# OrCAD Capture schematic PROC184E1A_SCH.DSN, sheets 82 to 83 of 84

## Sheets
82 61. AUDIO I/F - CODEC: size C; title: AUDIO I/F CODEC; note: PROC184_SCH
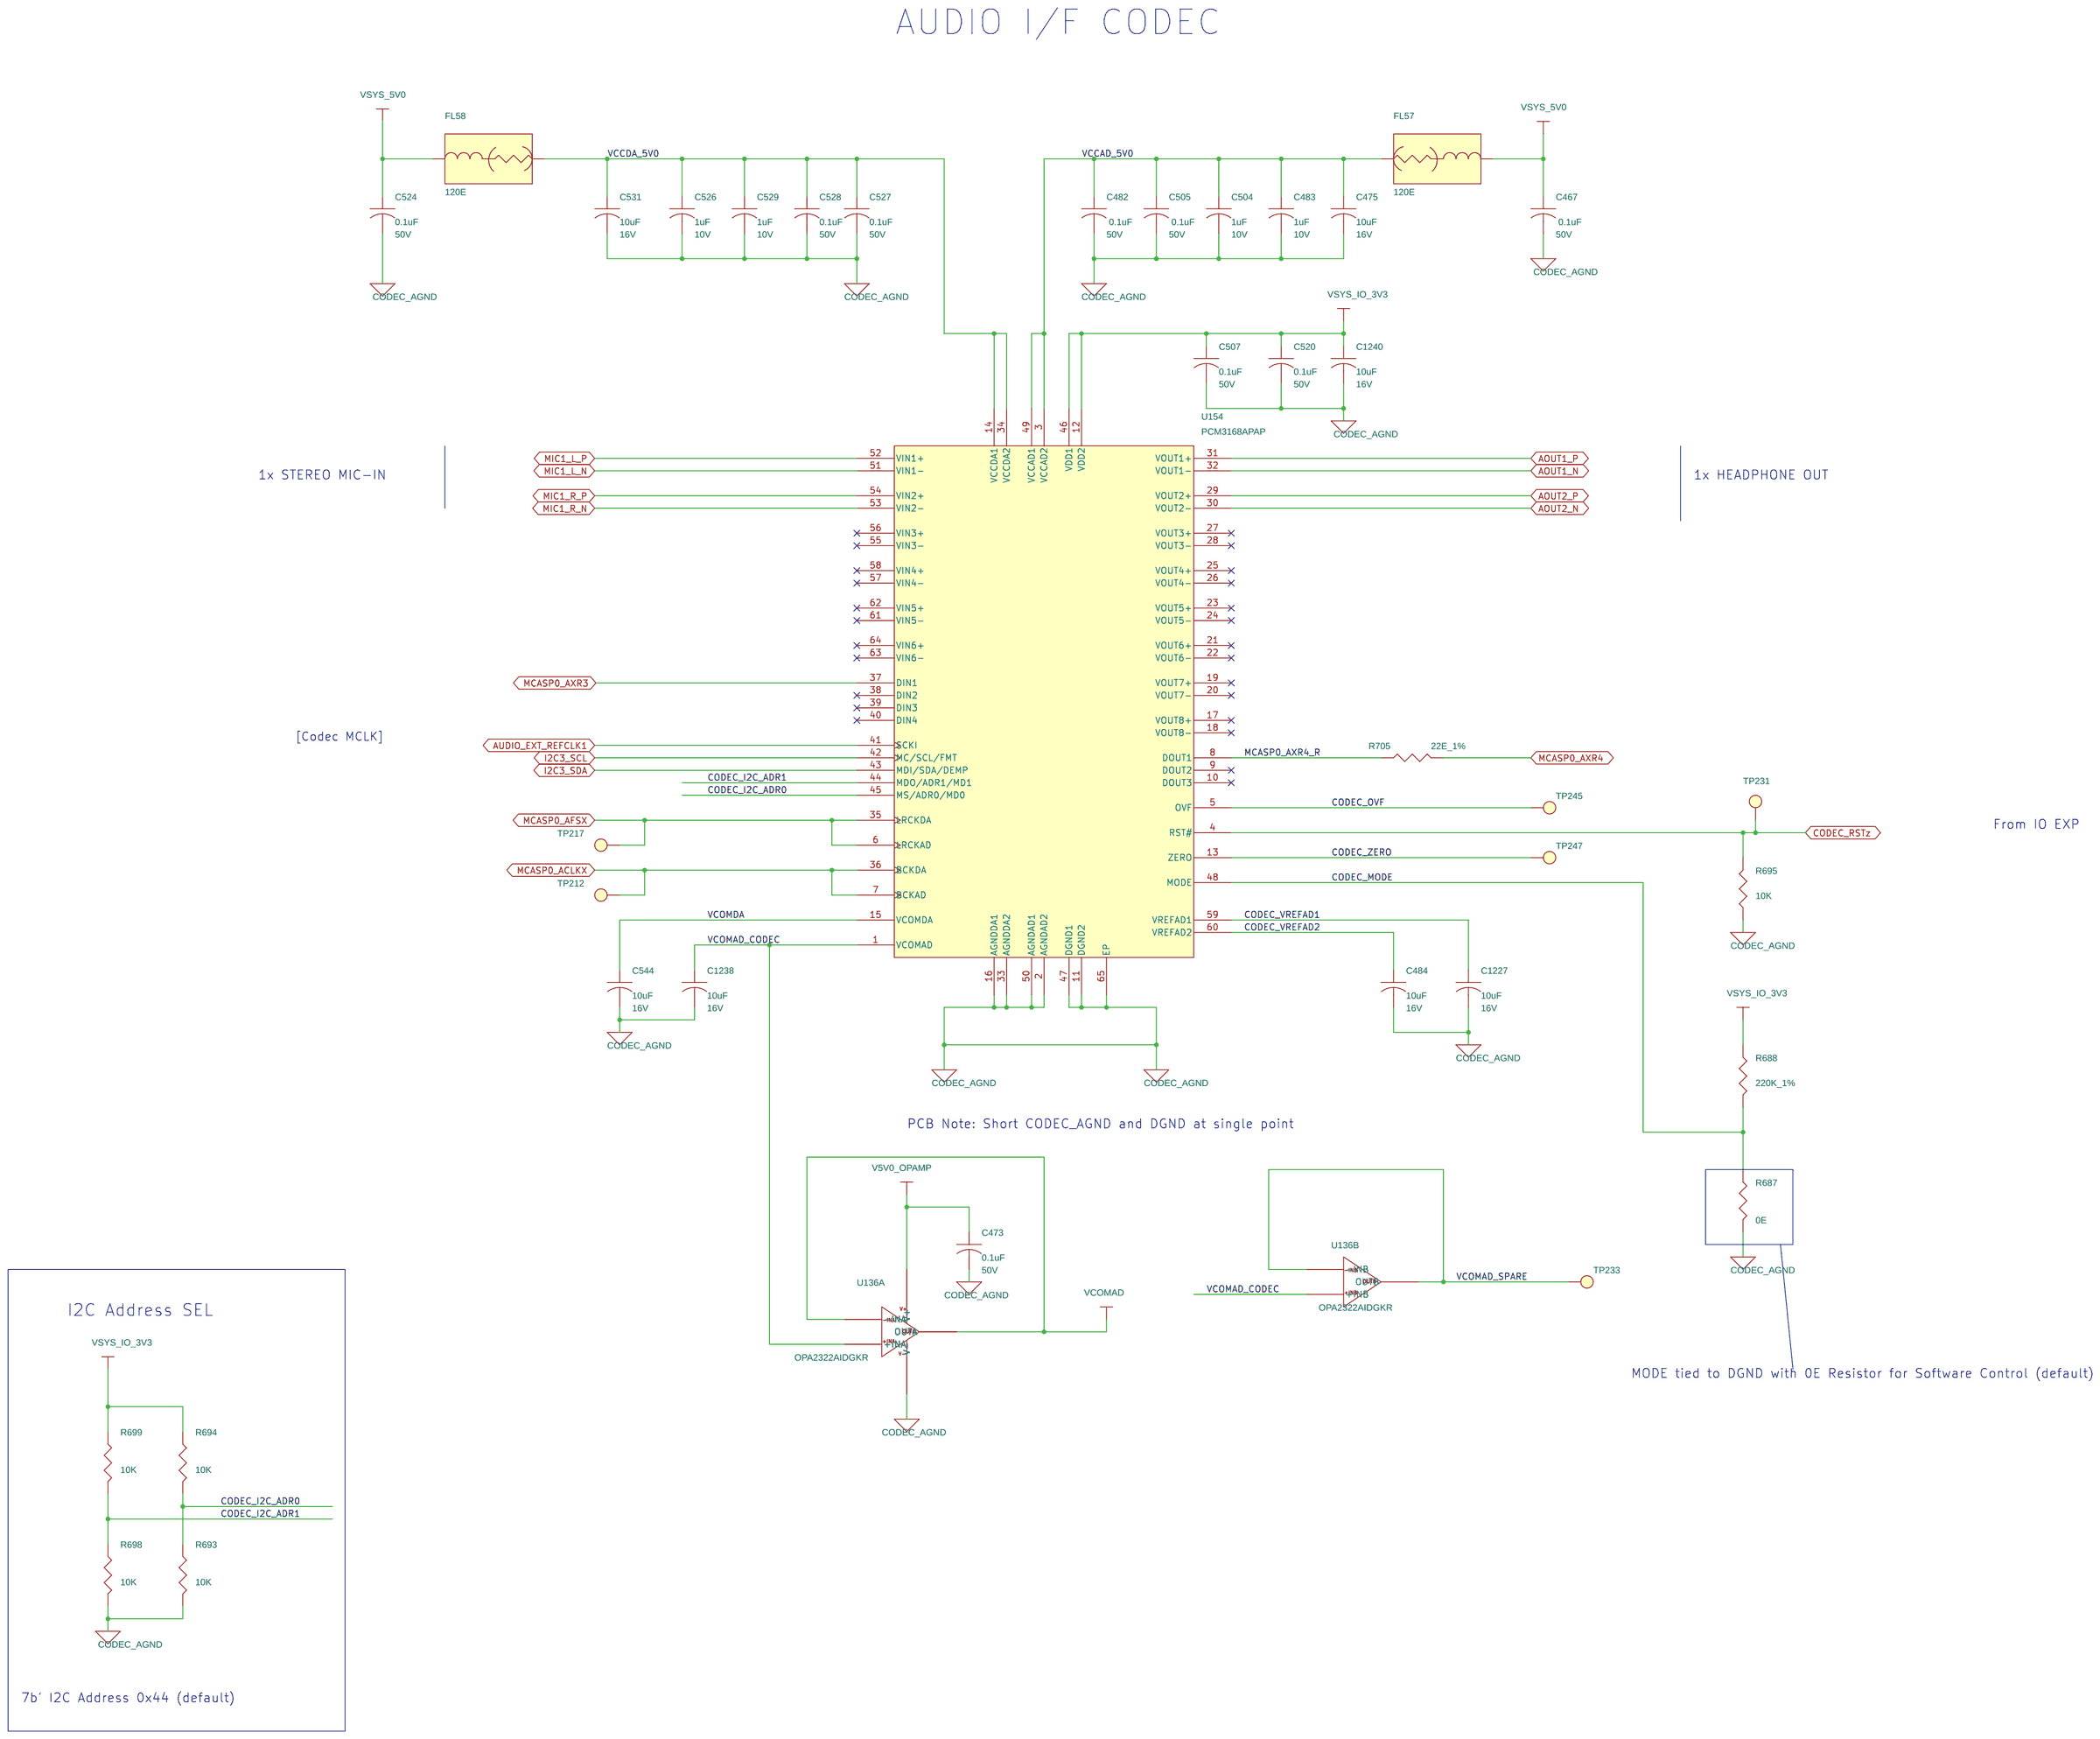
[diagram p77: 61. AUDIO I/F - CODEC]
83 63. AUDIO I/F - STEREO LOUT 1: size C; title: AUDIO I/F - STEREO LINE OUT & HP OUT# 1; note: PROC184_SCH
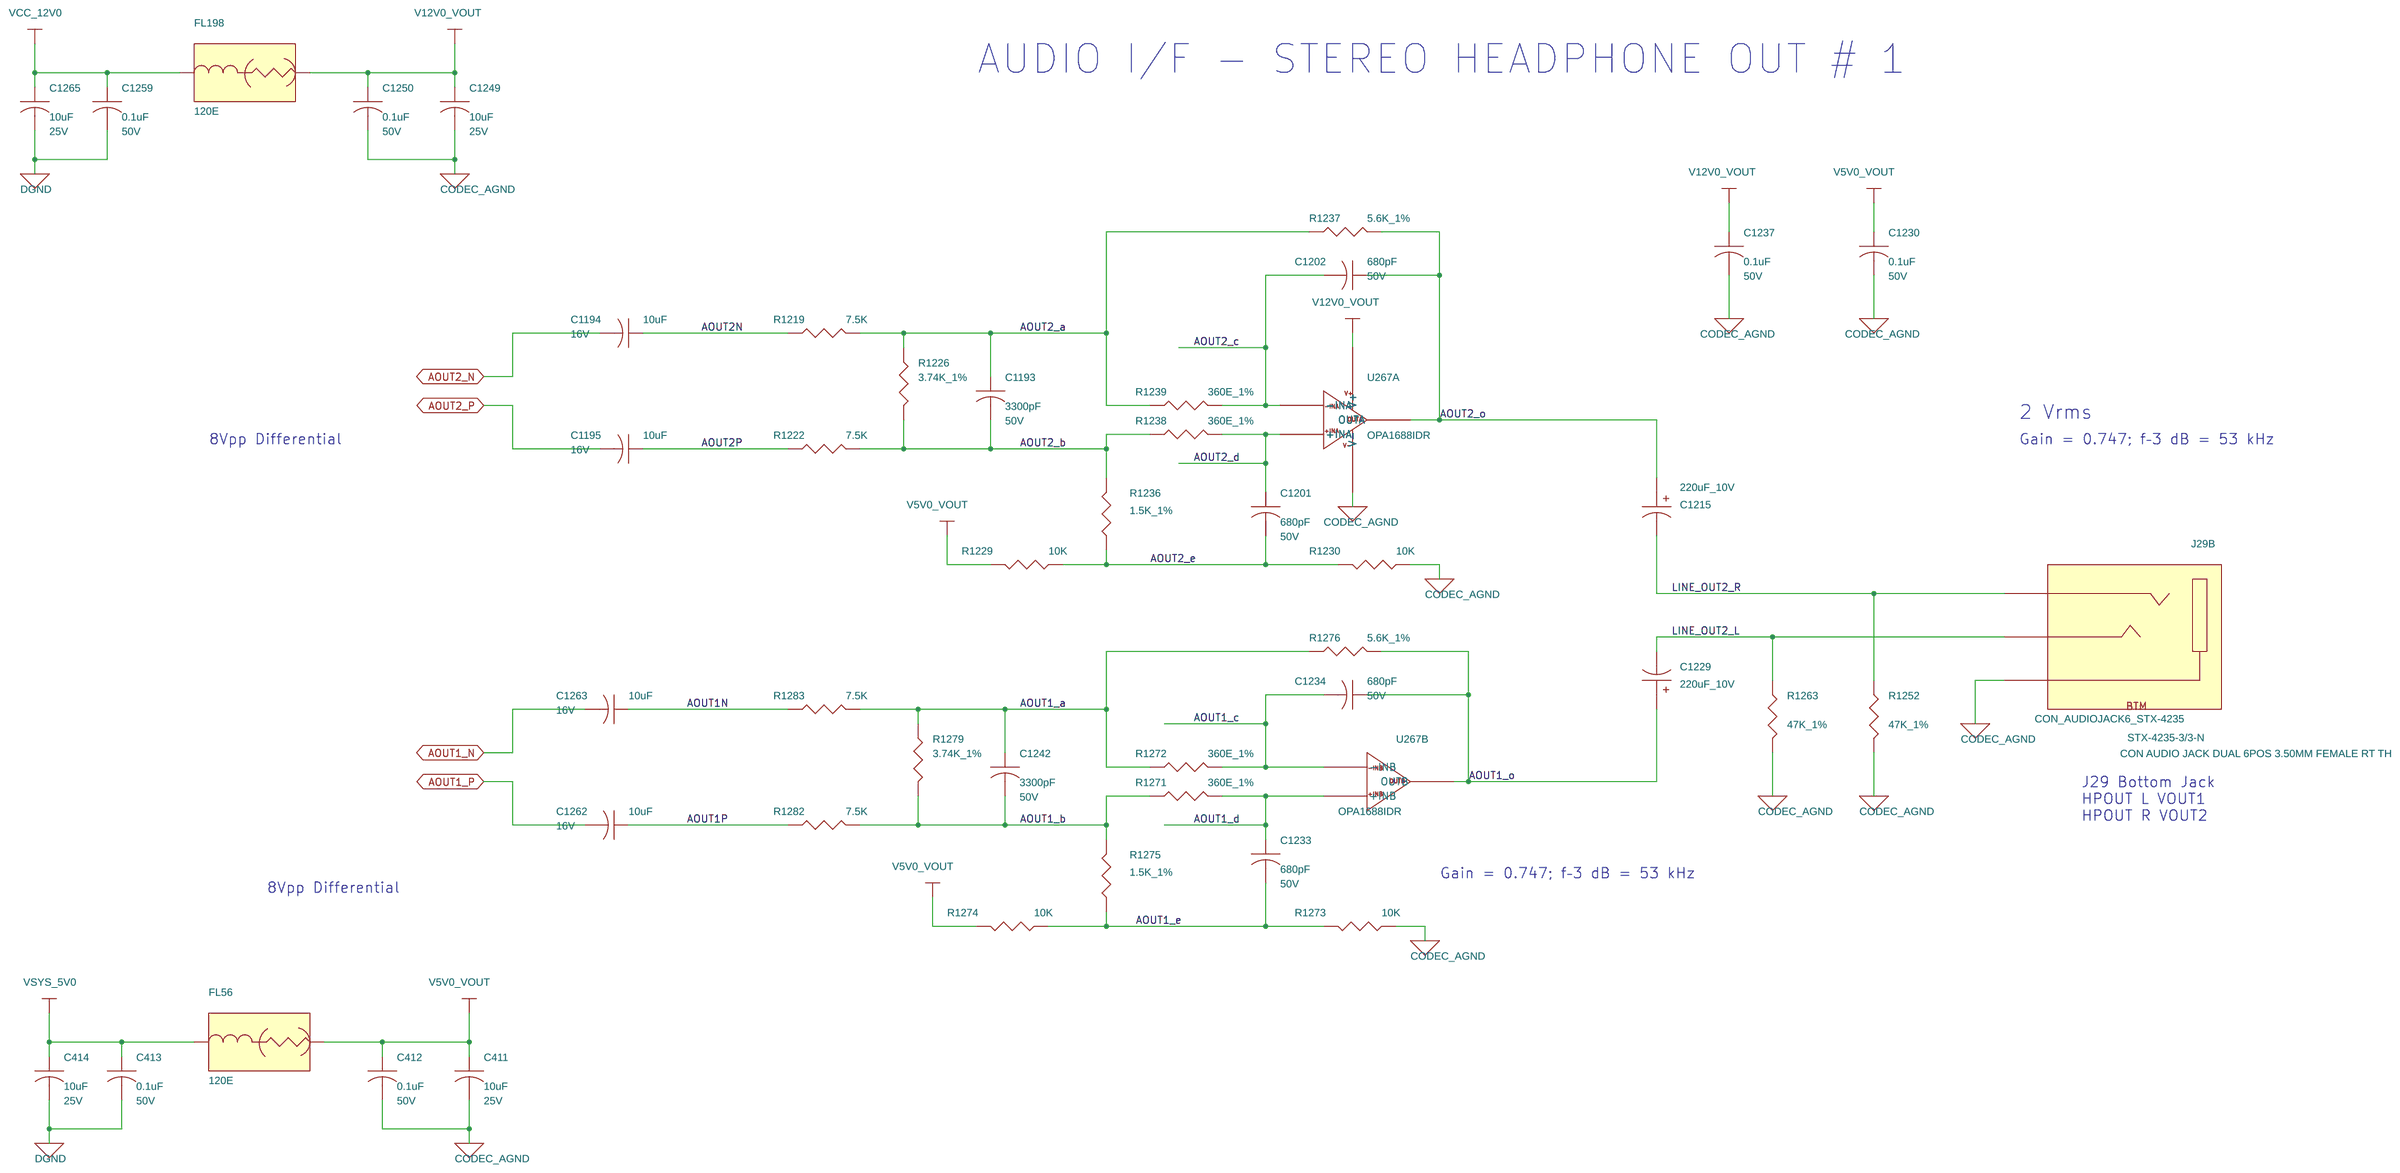
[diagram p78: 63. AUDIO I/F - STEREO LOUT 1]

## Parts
sheet 61. AUDIO I/F - CODEC
C467  0.1uF  [CAP0402_0-75]
C473  0.1uF  [CAP0402_0-75]
C475  10uF  [CAP0805_1-5]
C482  0.1uF  [CAP0402_0-75]
C483  1uF  [CAP0402_0-75]
C484  10uF  [CAP0805_1-5]
C504  1uF  [CAP0402_0-75]
C505  0.1uF  [CAP0402_0-75]
C507  0.1uF  [CAP0402_0-75]
C520  0.1uF  [CAP0402_0-75]
C524  0.1uF  [CAP0402_0-75]
C526  1uF  [CAP0402_0-75]
C527  0.1uF  [CAP0402_0-75]
C528  0.1uF  [CAP0402_0-75]
C529  1uF  [CAP0402_0-75]
C531  10uF  [CAP0805_1-5]
C544  10uF  [CAP0805_1-5]
C1227  10uF  [CAP0805_1-5]
C1238  10uF  [CAP0805_1-5]
C1240  10uF  [CAP0805_1-5]
FL57  120E  [EMIFIL_BLM15A_0402_0-6]
FL58  120E  [EMIFIL_BLM15A_0402_0-6]
R687  0E  [RES0402_0-5]
R688  220K_1%  [RES0402_0-5]
R693  10K  [RES0402_0-5]
R694  10K  [RES0402_0-5]
R695  10K  [RES0402_0-5]
R698  10K  [RES0402_0-5]
R699  10K  [RES0402_0-5]
R705  22E_1%  [RES0402_0-5]
TP212  TP40_SMD  [TP40_SMD]
TP217  TP40_SMD  [TP40_SMD]
TP231  TP40_SMD  [TP40_SMD]
TP233  TP40_SMD  [TP40_SMD]
TP245  TP40_SMD  [TP40_SMD]
TP247  TP40_SMD  [TP40_SMD]
U136  OPA2322AIDGKR  [VSSOP8_25-59_120X120_1-1]  (sections A,B)
U154  PCM3168APAP  [HTQFP64_19-68_400X400_1-2_EP7-3X7]
sheet 62. AUDIO I/F - STEREO MIC #1
J29  CON_AUDIOJACK6_STX-4235  [CON_AV6_STX-4235-3-3_S_R_T_26]  (sections A,B)
sheet 63. AUDIO I/F - STEREO LOUT 1
C411  10uF  [CAP0603_1-25]
C412  0.1uF  [CAP0402_0-75]
C413  0.1uF  [CAP0402_0-75]
C414  10uF  [CAP0603_1-25]
C1193  3300pF  [CAP0402_0-75]
C1194  10uF  [CAP0805_1-5]
C1195  10uF  [CAP0805_1-5]
C1201  680pF  [CAP0402_0-75]
C1202  680pF  [CAP0402_0-75]
C1215  220uF_10V  [CAPT3528T_1-25]
C1229  220uF_10V  [CAPT3528T_1-25]
C1230  0.1uF  [CAP0402_0-75]
C1233  680pF  [CAP0402_0-75]
C1234  680pF  [CAP0402_0-75]
C1237  0.1uF  [CAP0402_0-75]
C1242  3300pF  [CAP0402_0-75]
C1249  10uF  [CAP0603_1-25]
C1250  0.1uF  [CAP0402_0-75]
C1259  0.1uF  [CAP0402_0-75]
C1262  10uF  [CAP0805_1-5]
C1263  10uF  [CAP0805_1-5]
C1265  10uF  [CAP0603_1-25]
FL56  120E  [EMIFIL_BLM15A_0402_0-6]
FL198  120E  [EMIFIL_BLM15A_0402_0-6]
R1219  7.5K  [RES0402_0-5]
R1222  7.5K  [RES0402_0-5]
R1226  3.74K_1%  [RES0402_0-5]
R1229  10K  [RES0402_0-5]
R1230  10K  [RES0402_0-5]
R1236  1.5K_1%  [RES0402_0-5]
R1237  5.6K_1%  [RES0402_0-5]
R1238  360E_1%  [RES0402_0-5]
R1239  360E_1%  [RES0402_0-5]
R1252  47K_1%  [RES0402_0-5]
R1263  47K_1%  [RES0402_0-5]
R1271  360E_1%  [RES0402_0-5]
R1272  360E_1%  [RES0402_0-5]
R1273  10K  [RES0402_0-5]
R1274  10K  [RES0402_0-5]
R1275  1.5K_1%  [RES0402_0-5]
R1276  5.6K_1%  [RES0402_0-5]
R1279  3.74K_1%  [RES0402_0-5]
R1282  7.5K  [RES0402_0-5]
R1283  7.5K  [RES0402_0-5]
U267  OPA1688IDR  [SOIC8_1-8]  (sections A,B)

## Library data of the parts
C412 C413 C467 C473 C482 C505 C507 C520 C524 C527 C528 C1230 C1237 C1250 C1259 = CAP: CAP CERAMIC 0.1uF 50V 10% X7R 0402; Automotive Alternate_mfr_name: TDK; Automotive Alternate_mfr_part_number: CGA2B3X7R1H104K050BB; Chkd/date: MANIRAJA/261020; Crtd /date: ALVY/211020; Custom_Duty: 15%; Customs_HS_Code: 85322990; Direct Alternate_mfr_name: TDK; Direct Alternate_mfr_part_number: C1005X7R1H104K050BE; Distributor_name: DIGIKEY; Distributor_part_number: 490-10700-1-ND; Footprint Path: Y:\MIS_DATABASE\Library\ALTIUM_TOOL\PCB_FOOTPRINTS\Altium_Footprint_Lib.PcbLib; Height: 0.55MM; Library Path: Y:\MIS_DATABASE\Library\ALTIUM_TOOL\SCHEMATICS_PARTS\MS_DISCRETE_Library.schlib; Manufacturer: MURATA; Mfr_name: MURATA; Mfr_part_number: GRM155R71H104KE14D; Mistral Part No: 120011100014-R; Package: 0402; Part_type: CAPACITORS\CERAMIC; Project: J7_CP; RoHS: RoHS; Temperature: -55°C+125°C; Tolerance: 10%; Voltage: 50V; Wattage: NA; Weight: 3.1mg; Datasheet: Y:\MIS_DATABASE\DATASHEETS\CAPACITORS\GRM155R71H104KE14.PDF
C475 C484 C531 C544 C1194 C1195 C1227 C1238 C1240 C1262 C1263 = CAP: CAP CERAMIC 10uF 16V 10% X5R 0805; Automotive Alternate_mfr_name: TDK; Automotive Alternate_mfr_part_number: CGA4J1X7S1C106K125AC; Chkd/date: SHREESHAIL/220506; Crtd /date: MAZHAR/150506; Custom_Duty: 15%; Customs_HS_Code: 85322990; Direct Alternate_mfr_name: TDK; Direct Alternate_mfr_part_number: C2012X7S1C106K125AC; Distributor_name: DIGIKEY; Distributor_part_number: 490-3886-1-ND; Footprint Path: Y:\MIS_DATABASE\Library\ALTIUM_TOOL\PCB_FOOTPRINTS\Altium_Footprint_Lib.PcbLib; Height: 1.35MM; Library Path: Y:\MIS_DATABASE\Library\ALTIUM_TOOL\SCHEMATICS_PARTS\MS_DISCRETE_Library.schlib; Manufacturer: MURATA; Mfr_name: MURATA; Mfr_part_number: GRM21BR61C106KE15L; Mistral Part No: 120009030205-R; Package: 0805; Part_type: CAPACITORS\CERAMIC; Project: VOCERA; RoHS: RoHS; Temperature: -55°C+85°C; Tolerance: 10%; Voltage: 16V; Wattage: NA; Weight: 9.5mg; Datasheet: Y:\MIS_DATABASE\DATASHEETS\CAPACITORS\MURATA-GXX-SER_NOV17.PDF
C483 C504 C526 C529 = CAP: CAP CERAMIC 1uF 10V 10% X7S AUTO 0402; Automotive Alternate_mfr_name: TAIYO YUDEN; Automotive Alternate_mfr_part_number: EMK105BJ105KVHF; Chkd/date: MANIRAJA/100918; Crtd /date: ALVY/100918; Custom_Duty: 15%; Customs_HS_Code: 85322990; Direct Alternate_mfr_name: YAGEO AMERICA; Direct Alternate_mfr_part_number: CC0402KRX5R7BB105; Distributor_name: DIGIKEY; Distributor_part_number: 490-13409-1-ND; Footprint Path: Y:\MIS_DATABASE\Library\ALTIUM_TOOL\PCB_FOOTPRINTS\Altium_Footprint_Lib.PcbLib; Height: 0.70MM; Library Path: Y:\MIS_DATABASE\Library\ALTIUM_TOOL\SCHEMATICS_PARTS\MS_DISCRETE_Library.schlib; Manufacturer: TDK CORPORATION; Mfr_name: MURATA; Mfr_part_number: GCM155C71A105KE38D; Mistral Part No: 120018090021-R; Package: 0402; Part_type: CAPACITORS\CERAMIC; Project: SMART-M_SCRIPTALK_PB; RoHS: RoHS; Temperature: -55°C+125°C; Tolerance: 10%; Voltage: 10V; Wattage: NA; Weight: 6mg; Datasheet: Y:\MIS_DATABASE\DATASHEETS\CAPACITORS\MURATA-GCM-SER.PDF
FL56-FL58 FL198 = EMIFILTER_IND: IND FERRITE BEAD CHIP 120E 1.3A 0402; Automotive Alternate_mfr_name: TDK; Automotive Alternate_mfr_part_number: MPZ1005S121CTD25; Chkd/date: VASANTHA/010117; Crtd /date: CHAITHANYA/150312; Custom_Duty: 24%; Customs_HS_Code: 85437099; Direct Alternate_mfr_name: TDK; Direct Alternate_mfr_part_number: MPZ1005S121CT000; Distributor_name: DIGIKEY; Distributor_part_number: 490-5203-1-ND; Footprint Path: Y:\MIS_DATABASE\Library\ALTIUM_TOOL\PCB_FOOTPRINTS\Altium_Footprint_Lib.PcbLib; Height: 0.55MM; Library Path: Y:\MIS_DATABASE\Library\ALTIUM_TOOL\SCHEMATICS_PARTS\MS_FILTER_Library.schlib; Manufacturer: MURATA; Mfr_name: MURATA; Mfr_part_number: BLM15PD121SN1D; Mistral Part No: 130012030043-R; Package: 0402; Part_type: FILTER; Project: GEN_3-8; RoHS: RoHS; Temperature: -55°C+125°C; Tolerance: 25%; Voltage: NA; Wattage: NA; Weight: 0.65mg; Datasheet: Y:\MIS_DATABASE\DATASHEETS\DISCRETES\INDUCTORS\BLM15X-SER.PDF
R687 = RESISTOR: RES 0E 1/10W JUMPER 0402; Chkd/date: VASANTHA/061216; Crtd /date: NAVEED/201014; Custom_Duty: 15%; Customs_HS_Code: 85332119; Distributor_name: DIGIKEY; Distributor_part_number: P0.0JCT-ND; Footprint Path: Y:\MIS_DATABASE\Library\ALTIUM_TOOL\PCB_FOOTPRINTS\Altium_Footprint_Lib.PcbLib; Height: 0.40MM; IBISSP_MODLES: VALUE REPEATING 2 TIME; Library Path: Y:\MIS_DATABASE\Library\ALTIUM_TOOL\SCHEMATICS_PARTS\MS_DISCRETE_Library.schlib; Manufacturer: PANASONIC-ECG; Mfr_name: PANASONIC-ECG; Mfr_part_number: ERJ-2GE0R00X; Mistral Part No: 110018030052-R; Package: 0402; Part_type: RESISTORS\FIXED; Project: AEGIS POM; RoHS: RoHS; Temperature: -55°C+155°C; Tolerance: NA; Voltage: NA; Wattage: 1/10W; Weight: 0.8mg; Datasheet: Y:\MIS_DATABASE\DATASHEETS\RESISTORS\PAN-ERJSER_NOV17.PDF
R688 = RESISTOR: RES 220K 1/16W 1% 0402; Assembly_Instruction: DNI; Chkd/date: MANIRAJA/230817; Crtd /date: MANIRAJA/230817; Custom_Duty: 15%; Customs_HS_Code: 85332119; Distributor_name: DIGIKEY; Distributor_part_number: 541-220KLCT-ND; Footprint Path: Y:\MIS_DATABASE\Library\ALTIUM_TOOL\PCB_FOOTPRINTS\Altium_Footprint_Lib.PcbLib; Height: 0.40MM; Library Path: Y:\MIS_DATABASE\Library\ALTIUM_TOOL\SCHEMATICS_PARTS\MS_DISCRETE_Library.schlib; Manufacturer: VISHAY; Mfr_name: VISHAY; Mfr_part_number: CRCW0402220KFKED; Mistral Part No: 110017080025-R; Package: 0402; Part_type: RESISTORS\FIXED; Project: TI_MAXIE_CPB; RoHS: RoHS; Temperature: -55°C+155°C; Tolerance: 1%; Voltage: NA; Wattage: 1/16W; Weight: 0.65mg; Datasheet: Y:\MIS_DATABASE\DATASHEETS\RESISTORS\CRCW0603.PDF
R693 R695 R698 R1229 R1230 R1273 R1274 = RESISTOR: RES 10K 1/16W 5% 0402; Chkd/date: VASANTHA/061216; Crtd /date: MAZHAR/230805; Custom_Duty: 15%; Customs_HS_Code: 85332119; Distributor_name: DIGIKEY; Distributor_part_number: 311-10KJRCT-ND; Footprint Path: Y:\MIS_DATABASE\Library\ALTIUM_TOOL\PCB_FOOTPRINTS\Altium_Footprint_Lib.PcbLib; Height: 0.40MM; Library Path: Y:\MIS_DATABASE\Library\ALTIUM_TOOL\SCHEMATICS_PARTS\MS_DISCRETE_Library.schlib; Manufacturer: YAGEO AMERICA; Mfr_name: YAGEO AMERICA; Mfr_part_number: RC0402JR-0710KL; Mistral Part No: 110011060021-R; Package: 0402; Part_type: RESISTORS\FIXED; Project: HSE; RoHS: RoHS; Temperature: -55°C+155°C; Tolerance: 5%; Voltage: NA; Wattage: 1/16W; Weight: 0.65mg; Datasheet: Y:\MIS_DATABASE\DATASHEETS\RESISTORS\RCXXXXL-SER_MAR18.PDF
R694 R699 = RESISTOR: RES 10K 1/16W 5% 0402; Assembly_Instruction: DNI; Chkd/date: VASANTHA/061216; Crtd /date: MAZHAR/230805; Custom_Duty: 15%; Customs_HS_Code: 85332119; Distributor_name: DIGIKEY; Distributor_part_number: 311-10KJRCT-ND; Footprint Path: Y:\MIS_DATABASE\Library\ALTIUM_TOOL\PCB_FOOTPRINTS\Altium_Footprint_Lib.PcbLib; Height: 0.40MM; Library Path: Y:\MIS_DATABASE\Library\ALTIUM_TOOL\SCHEMATICS_PARTS\MS_DISCRETE_Library.schlib; Manufacturer: YAGEO AMERICA; Mfr_name: YAGEO AMERICA; Mfr_part_number: RC0402JR-0710KL; Mistral Part No: 110011060021-R; Package: 0402; Part_type: RESISTORS\FIXED; Project: HSE; RoHS: RoHS; Temperature: -55°C+155°C; Tolerance: 5%; Voltage: NA; Wattage: 1/16W; Weight: 0.65mg; Datasheet: Y:\MIS_DATABASE\DATASHEETS\RESISTORS\RCXXXXL-SER_MAR18.PDF
R705 = RESISTOR: RES 22E 1/16W 1% 0402; Chkd/date: SUHAS/290910; Crtd /date: MAZHAR/090909; Cust_part_number: 4700-80047E; Custom_Duty: 15%; Customs_HS_Code: 85332119; Distributor_name: DIGIKEY; Distributor_part_number: 311-22.0LRCT-ND; Footprint Path: Y:\MIS_DATABASE\Library\ALTIUM_TOOL\PCB_FOOTPRINTS\Altium_Footprint_Lib.PcbLib; Height: 0.40MM; Library Path: Y:\MIS_DATABASE\Library\ALTIUM_TOOL\SCHEMATICS_PARTS\MS_DISCRETE_Library.schlib; Manufacturer: YAGEO AMERICA; Mfr_name: YAGEO AMERICA; Mfr_part_number: RC0402FR-0722RL; Mistral Part No: 110009090004-R; Package: 0402; Part_type: RESISTORS\FIXED; Project: VMEFMCD; RoHS: RoHS; Temperature: -55°C+155°C; Tolerance: 1%; Voltage: NA; Wattage: 1/16W; Weight: 0.65mg; Datasheet: Y:\MIS_DATABASE\DATASHEETS\RESISTORS\RCXXXXL-SER_MAR18.PDF
TP212 TP217 TP231 TP233 TP245 TP247 = TESTPOINT: TESTPOINT CIR 40 SMD; Chkd/date: MAZHAR/190505; Crtd /date: MAZHAR/190505; Distributor_name: NA; Distributor_part_number: NA; Footprint Path: Y:\MIS_DATABASE\Library\ALTIUM_TOOL\PCB_FOOTPRINTS\Altium_Footprint_Lib.PcbLib; Height: NA; Library Path: Y:\MIS_DATABASE\Library\ALTIUM_TOOL\SCHEMATICS_PARTS\MS_DISCRETE_Library.schlib; MECHANICAL 3D STEP FILE: NA; Manufacturer: LOCAL; Mfr_name: LOCAL; Mistral Part No: 130009030933; Package: SMD; Project: RAINIER-3; RoHS: NA; Temperature: NA; Tolerance: NA; Voltage: NA; Wattage: NA; Weight: NA; Datasheet: NA
U136 = OPA2350UA_SOIC8: IC 20MHz 1.8V LOW NOISE RRI/O CMOS OPAMP VSSOP8; Automotive Alternate_mfr_name: TEXAS INSTRUMENTS; Automotive Alternate_mfr_part_number: OPA2322AQDGKRQ1; Chkd/date: MANIRAJA/161018; Crtd /date: ALVY/161018; Custom_Duty: 15%; Customs_HS_Code: 85423100; Distributor_name: DIGIKEY; Distributor_part_number: 296-41349-1-ND; Footprint Path: Y:\MIS_DATABASE\Library\ALTIUM_TOOL\PCB_FOOTPRINTS\Altium_Footprint_Lib.PcbLib; Height: 1.10MM; Library Path: Y:\MIS_DATABASE\Library\ALTIUM_TOOL\SCHEMATICS_PARTS\MS_OPAMP_Library.schlib; Manufacturer: TEXAS INSTRUMENTS; Mfr_name: TEXAS INSTRUMENTS; Mistral Part No: 140118100019-R; Package: VSSOP8; Part_type: ICS\ANALOG\OPAMP; Project: TI_J7ES_EVM_CP; RoHS: RoHS; Temperature: -40°C+125°C; Tolerance: NA; Voltage: NA; Wattage: NA; Weight: 26.5mg; Datasheet: Y:\MIS_DATABASE\DATASHEETS\ICS\OPAMP\OPA2322XX.PDF
U154 = PCM3168APAP_HTQFP64_TI: IC 24BIT 96KHz/192KHz 6-IN/8-OUT AUDIO CODEC WITH DIFFERENTIAL IN/OUT HTQFP64; Automotive Alternate_mfr_name: TEXAS INSTRUMENTS; Automotive Alternate_mfr_part_number: PCM3168ATPAPRQ1; Chkd/date: MANIRAJA/140618; Crtd /date: ALVY/140618; Custom_Duty: 15%; Customs_HS_Code: 85423100; Distributor_name: DIGIKEY; Distributor_part_number: 296-23899-5-ND; Footprint Path: Y:\MIS_DATABASE\Library\ALTIUM_TOOL\PCB_FOOTPRINTS\Altium_Footprint_Lib.PcbLib; Height: 1.20MM; Library Path: Y:\MIS_DATABASE\Library\ALTIUM_TOOL\SCHEMATICS_PARTS\MS_TELECOM_Library.schlib; Library Ref: PCM3168APAP_HTQFP64; Manufacturer: TEXAS INSTRUMENTS; Mfr_name: TEXAS INSTRUMENTS; Mistral Part No: 143018060003-R; Package: HTQFP64; Part_type: ICS\TELECOM\CODEC; Project: TI_J7SVB_FMZ-BOARD; RoHS: RoHS; Temperature: -40°C+85°C; Tolerance: NA; Voltage: NA; Wattage: NA; Weight: 258.2mg; Datasheet: Y:\MIS_DATABASE\DATASHEETS\ICS\DIGITAL\CODEC\PCM3168A.PDF
J29 = CON_AUDIOJACK6_STX-4235-3_3: CON AUDIO JACK DUAL 6POS 3.50MM FEMALE RT TH; Chkd/date: MANIRAJA/090818; Crtd /date: ALVY/080818; Custom_Duty: 24%; Customs_HS_Code: 85369090; Distributor_name: MOUSER; Distributor_part_number: 806-STX-4235-3/3-N; Footprint Path: Y:\MIS_DATABASE\Library\ALTIUM_TOOL\PCB_FOOTPRINTS\Altium_Footprint_Lib.PcbLib; Height: 26.00MM; Library Path: Y:\MIS_DATABASE\Library\ALTIUM_TOOL\SCHEMATICS_PARTS\MS_CONNECTOR_Library.schlib; Library Ref: CON_AUDIOJACK6_STX-4235-3/3; Manufacturer: KYCON; Mfr_name: KYCON; Mfr_part_number: STX-4235-3/3-N; Mistral Part No: 150018080005-R; Package: THRU-HOLE; Part_type: CONNECTOR\JACK; Project: TI_J7ES_EVM_FUSION2_SER_CAP; RoHS: RoHS; Temperature: -25°C+85°C; Tolerance: NA; Voltage: NA; Wattage: NA; Weight: NA; Datasheet: Y:\MIS_DATABASE\DATASHEETS\CONNECTORS\STX-4235-3-3-N.PDF
C411 C414 C1249 C1265 = CAP: CAP CERAMIC 10uF 25V 20% X5R 0603; Automotive Alternate_mfr_name: MURATA; Automotive Alternate_mfr_part_number: GRT188R61E106ME13D; Chkd/date: MANIRAJA/040718; Crtd /date: MANIRAJA/040718; Custom_Duty: 15%; Customs_HS_Code: 85322990; Direct Alternate_mfr_name: TDK; Direct Alternate_mfr_part_number: C1608X5R1E106M080AC; Distributor_name: DIGIKEY; Distributor_part_number: 490-10991-1-ND; Footprint Path: Y:\MIS_DATABASE\Library\ALTIUM_TOOL\PCB_FOOTPRINTS\Altium_Footprint_Lib.PcbLib; Height: 1.20MM; Library Path: Y:\MIS_DATABASE\Library\ALTIUM_TOOL\SCHEMATICS_PARTS\MS_DISCRETE_Library.schlib; Manufacturer: MURATA; Mfr_name: MURATA; Mfr_part_number: ZRB18AR61E106ME01L; Mistral Part No: 120018070001-R; Package: 0603; Part_type: CAPACITORS\CERAMIC; Project: CABS_VME_DIO; RoHS: RoHS; Temperature: -55°C+85°C; Tolerance: 20%; Voltage: 25V; Wattage: NA; Weight: 2mg; Datasheet: Y:\MIS_DATABASE\DATASHEETS\CAPACITORS\ZRB18AR61E106ME01L.PDF
C1193 C1242 = CAP: CAP CERAMIC 3300pF 50V 10% X7R 0402; Automotive Alternate_mfr_name: TDK; Automotive Alternate_mfr_part_number: CGA2B2X7R1H332M050BA; Chkd/date: MANIRAJA/180817; Crtd /date: MANIRAJA/180817; Custom_Duty: 15%; Customs_HS_Code: 85322990; Direct Alternate_mfr_name: SAMSUNG; Direct Alternate_mfr_part_number: CL05B332KB5NNNC; Distributor_name: DIGIKEY; Distributor_part_number: 490-3248-1-ND; Footprint Path: Y:\MIS_DATABASE\Library\ALTIUM_TOOL\PCB_FOOTPRINTS\Altium_Footprint_Lib.PcbLib; Height: 0.55MM; Library Path: Y:\MIS_DATABASE\Library\ALTIUM_TOOL\SCHEMATICS_PARTS\MS_DISCRETE_Library.schlib; Manufacturer: MURATA; Mfr_name: MURATA; Mfr_part_number: GRM155R71H332KA01D; Mistral Part No: 120009030367-R; Package: 0402; Part_type: CAPACITORS\CERAMIC; Project: DM8147_PCI CARD; RoHS: RoHS; Temperature: -55°C+125°C; Tolerance: 10%; Voltage: 50V; Wattage: NA; Weight: 6mg; Datasheet: Y:\MIS_DATABASE\DATASHEETS\CAPACITORS\MURATA-GXX-SER_NOV17.PDF
C1201 C1202 C1233 C1234 = CAP: CAP CERAMIC 680pF 50V 5% X7R 0402; Automotive Alternate_mfr_name: TDK; Automotive Alternate_mfr_part_number: CGA2B2X7R1H681K050BA; Chkd/date: BAVISH/260911; Crtd /date: CHAITHANYA/260911; Custom_Duty: 15%; Customs_HS_Code: 85322990; Direct Alternate_mfr_name: SAMSUNG; Direct Alternate_mfr_part_number: CL05B681KB5NNNC; Distributor_name: DIGIKEY; Distributor_part_number: 478-5270-1-ND; Footprint Path: Y:\MIS_DATABASE\Library\ALTIUM_TOOL\PCB_FOOTPRINTS\Altium_Footprint_Lib.PcbLib; Height: 0.56MM; Library Path: Y:\MIS_DATABASE\Library\ALTIUM_TOOL\SCHEMATICS_PARTS\MS_DISCRETE_Library.schlib; Manufacturer: AVX CORPORATION; Mfr_name: AVX CORPORATION; Mfr_part_number: 04025C681JAT2A; Mistral Part No: 120011090031-R; Package: 0402; Part_type: CAPACITORS\CERAMIC; Project: GEMYC; RoHS: RoHS; Temperature: -55°C+125°C; Tolerance: 5%; Voltage: 50V; Wattage: NA; Weight: 0.65mg; Datasheet: Y:\MIS_DATABASE\DATASHEETS\CAPACITORS\AVX_MLC.PDF
C1215 C1229 = CAP_POL: CAP TANTALUM 220uF 10V 20% ESR 1.3E T3528; Chkd/date: MANIRAJA/081218; Crtd /date: MANIRAJA/081218; Custom_Duty: 15%; Customs_HS_Code: 85322990; Distributor_name: DIGIKEY; Distributor_part_number: 478-6612-1-ND; Footprint Path: Y:\MIS_DATABASE\Library\ALTIUM_TOOL\PCB_FOOTPRINTS\Altium_Footprint_Lib.PcbLib; Height: 1.20MM; Library Path: Y:\MIS_DATABASE\Library\ALTIUM_TOOL\SCHEMATICS_PARTS\MS_DISCRETE_Library.schlib; Manufacturer: AVX CORPORATION; Mfr_name: AVX CORPORATION; Mfr_part_number: TLNT227M010R1300; Mistral Part No: 120018120009-R; Package: T3528; Part_type: CAPACITORS\TANTALUM; Project: TI_J7ES_EVM_CP; RoHS: RoHS; Temperature: -55°C+125°C; Tolerance: 20%; Voltage: 10V; Wattage: NA; Weight: 16mg; Datasheet: Y:\MIS_DATABASE\DATASHEETS\CAPACITORS\AVX_TLN-SER.PDF
R1219 R1222 R1282 R1283 = RESISTOR: RES 7.5K 1/16W 5% 0402; Chkd/date: MAZHAR/280108; Crtd /date: USMAN/280108; Custom_Duty: 15%; Customs_HS_Code: 85332119; Distributor_name: DIGIKEY; Distributor_part_number: 541-7.5KJCT-ND; Footprint Path: Y:\MIS_DATABASE\Library\ALTIUM_TOOL\PCB_FOOTPRINTS\Altium_Footprint_Lib.PcbLib; Height: 0.40MM; Library Path: Y:\MIS_DATABASE\Library\ALTIUM_TOOL\SCHEMATICS_PARTS\MS_DISCRETE_Library.schlib; Manufacturer: VISHAY; Mfr_name: VISHAY; Mfr_part_number: CRCW04027K50JNED; Mistral Part No: 110009031092-R; Package: 0402; Part_type: RESISTORS\FIXED; Project: TELEMETRY ENCODER; RoHS: RoHS; Temperature: -55°C+155°C; Tolerance: 5%; Voltage: NA; Wattage: 1/16W; Weight: 0.65mg; Datasheet: Y:\MIS_DATABASE\DATASHEETS\RESISTORS\CRCW0603.PDF
R1226 R1279 = RESISTOR: RES 3.74K 1/10W 1% 0402; Chkd/date: MAZHAR/151208; Crtd /date: USMAN/031208; Custom_Duty: 15%; Customs_HS_Code: 85332119; Distributor_name: DIGIKEY; Distributor_part_number: P3.74KLCT-ND; Footprint Path: Y:\MIS_DATABASE\Library\ALTIUM_TOOL\PCB_FOOTPRINTS\Altium_Footprint_Lib.PcbLib; Height: 0.40MM; Library Path: Y:\MIS_DATABASE\Library\ALTIUM_TOOL\SCHEMATICS_PARTS\MS_DISCRETE_Library.schlib; Manufacturer: PANASONIC-ECG; Mfr_name: PANASONIC-ECG; Mfr_part_number: ERJ-2RKF3741X; Mistral Part No: 110009030640-R; Package: 0402; Part_type: RESISTORS\FIXED; Project: KHAN_HSST; RoHS: RoHS; Temperature: -55°C+155°C; Tolerance: 1%; Voltage: NA; Wattage: 1/10W; Weight: 0.8mg; Datasheet: Y:\MIS_DATABASE\DATASHEETS\RESISTORS\PAN-ERJSER_NOV17.PDF
R1236 R1275 = RESISTOR: RES 1.5K 1/16W 1% 0402; Chkd/date: VASANTHA/201216; Crtd /date: JEBRAN/250815; Custom_Duty: 15%; Customs_HS_Code: 85332119; Distributor_name: DIGIKEY; Distributor_part_number: 311-1.50KLRCT-ND; Footprint Path: Y:\MIS_DATABASE\Library\ALTIUM_TOOL\PCB_FOOTPRINTS\Altium_Footprint_Lib.PcbLib; Height: 0.40MM; Library Path: Y:\MIS_DATABASE\Library\ALTIUM_TOOL\SCHEMATICS_PARTS\MS_DISCRETE_Library.schlib; Manufacturer: YAGEO AMERICA; Mfr_name: YAGEO AMERICA; Mfr_part_number: RC0402FR-071K5L; Mistral Part No: 110015080041-R; Package: 0402; Part_type: RESISTORS\FIXED; Project: OCTBTS3600; RoHS: RoHS; Temperature: -55°C+155°C; Tolerance: 1%; Voltage: NA; Wattage: 1/16W; Weight: 0.65mg; Datasheet: Y:\MIS_DATABASE\DATASHEETS\RESISTORS\RCXXXXL-SER_MAR18.PDF
R1237 R1276 = RESISTOR: RES 5.6K 1/16W 1% 0402; Chkd/date: MANIRAJA/050517; Crtd /date: MANIRAJA/050517; Custom_Duty: 15%; Customs_HS_Code: 85332119; Distributor_name: DIGIKEY; Distributor_part_number: 311-5.6KLRCT-ND; Footprint Path: Y:\MIS_DATABASE\Library\ALTIUM_TOOL\PCB_FOOTPRINTS\Altium_Footprint_Lib.PcbLib; Height: 0.40MM; Library Path: Y:\MIS_DATABASE\Library\ALTIUM_TOOL\SCHEMATICS_PARTS\MS_DISCRETE_Library.schlib; Manufacturer: YAGEO AMERICA; Mfr_name: YAGEO AMERICA; Mfr_part_number: RC0402FR-075K6L; Mistral Part No: 110011100024-R; Package: 0402; Part_type: RESISTORS\FIXED; Project: GOLDEN-I LITE; RoHS: RoHS; Temperature: -55°C+155°C; Tolerance: 1%; Voltage: NA; Wattage: 1/16W; Weight: 0.65mg; Datasheet: Y:\MIS_DATABASE\DATASHEETS\RESISTORS\RCXXXXL-SER_MAR18.PDF
R1238 R1239 R1271 R1272 = RESISTOR: RES 360E 1/10W 1% 0402; Chkd/date: MANIRAJA/190218; Crtd /date: ALVY/190218; Custom_Duty: 15%; Customs_HS_Code: 85332119; Distributor_name: DIGIKEY; Distributor_part_number: P360LCT-ND; Footprint Path: Y:\MIS_DATABASE\Library\ALTIUM_TOOL\PCB_FOOTPRINTS\Altium_Footprint_Lib.PcbLib; Height: 0.40MM; Library Path: Y:\MIS_DATABASE\Library\ALTIUM_TOOL\SCHEMATICS_PARTS\MS_DISCRETE_Library.schlib; Manufacturer: PANASONIC-ECG; Mfr_name: PANASONIC-ECG; Mfr_part_number: ERJ-2RKF3600X; Mistral Part No: 110018020033-R; Package: 0402; Part_type: RESISTORS\FIXED; Project: GRACO SMART MODULE; RoHS: RoHS; Temperature: -55°C+155°C; Tolerance: 1%; Voltage: NA; Wattage: 1/10W; Weight: 0.8mg; Datasheet: Y:\MIS_DATABASE\DATASHEETS\RESISTORS\PAN-ERJSER_NOV17.PDF
R1252 R1263 = RESISTOR: RES 47K 1/16W 1% 0402; Chkd/date: VASANTHA/060117; Crtd /date: MAZHAR/141206; Custom_Duty: 15%; Customs_HS_Code: 85332119; Distributor_name: DIGIKEY; Distributor_part_number: 311-47.0KLRCT-ND; Footprint Path: Y:\MIS_DATABASE\Library\ALTIUM_TOOL\PCB_FOOTPRINTS\Altium_Footprint_Lib.PcbLib; Height: 0.40MM; Library Path: Y:\MIS_DATABASE\Library\ALTIUM_TOOL\SCHEMATICS_PARTS\MS_DISCRETE_Library.schlib; Manufacturer: YAGEO AMERICA; Mfr_name: YAGEO AMERICA; Mfr_part_number: RC0402FR-0747KL; Mistral Part No: 110009030884-R; Package: 0402; Part_type: RESISTORS\FIXED; Project: ADR1B; RoHS: RoHS; Temperature: -55°C+155°C; Tolerance: 1%; Voltage: NA; Wattage: 1/16W; Weight: 0.65mg; Datasheet: Y:\MIS_DATABASE\DATASHEETS\RESISTORS\RCXXXXL-SER_MAR18.PDF
U267 = OPA2350UA_SOIC8: IC 36V SOUND PLUS 10MHz RAIL TO RAIL O/P OPAMP SOIC8; Chkd/date: MANIRAJA/121018; Crtd /date: MANIRAJA/121018; Custom_Duty: 15%; Customs_HS_Code: 85423100; Distributor_name: DIGIKEY; Distributor_part_number: 296-47272-1-ND; Footprint Path: Y:\MIS_DATABASE\Library\ALTIUM_TOOL\PCB_FOOTPRINTS\Altium_Footprint_Lib.PcbLib; Height: 1.75MM; Library Path: Y:\MIS_DATABASE\Library\ALTIUM_TOOL\SCHEMATICS_PARTS\MS_OPAMP_Library.schlib; Manufacturer: TEXAS INSTRUMENTS; Mfr_name: TEXAS INSTRUMENTS; Mistral Part No: 140118100003-R; Package: SOIC8; Part_type: ICS\ANALOG\OPAMP; Project: TI_J7ES_EVM_CP; RoHS: RoHS; Temperature: -40°C+85°C; Tolerance: NA; Voltage: NA; Wattage: NA; Weight: 76mg; Datasheet: Y:\MIS_DATABASE\DATASHEETS\ICS\OPAMP\OPA168XXX.PDF

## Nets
DGND: C411.2 C412.2 C413.2 C414.2 C467.2 C473.2 C475.2 C482.2 C483.2 C484.2 C504.2 C505.2 C507.2 C520.2 C524.2 C526.2 C527.2 C528.2 C529.2 C531.2 C544.2 C1227.2 C1230.2 C1237.2 C1238.2 C1240.2 C1249.2 C1250.2 C1259.2 C1265.2 J29.1B R687.2 R693.1 R695.1 R698.1 R1230.1 R1252.2 R1263.2 R1273.1 U136.4(V-) U154.2(AGNDAD2) U154.11(DGND2) U154.16(AGNDDA1) U154.33(AGNDDA2) U154.47(DGND1) U154.50(AGNDAD1) U154.65(EP) U267.4(V-) ; also on sheet 11 12 13 14 15 16 17 18 20 21 22 23 24 25 26 27 28 29 30 31 32 33 34 35 36 37 38 39 40 41 42 43 44 45 46 47 48 49 50 51 52 53 54 55 56 57 58 59 60 61 62 63 64 65 66 67 68 69 70 71 72 73 76 77 78 79 81 84
V5V0_OPAMP: C473.1 U136.8(V+) ; also on sheet 84
V5V0_VOUT: C411.1 C412.1 C1230.1 FL56.2 R1229.2 R1274.2
V12V0_VOUT: C1237.1 C1249.1 C1250.1 FL198.2 U267.8(V+)
VCC_12V0: C1259.1 C1265.1 FL198.1 ; also on sheet 30 31 46 50 53 59 60 64 66
VCCAD_5V0: C475.1 C482.1 C483.1 C504.1 C505.1 FL57.2 U154.3(VCCAD2) U154.49(VCCAD1)
VCCDA_5V0: C526.1 C527.1 C528.1 C529.1 C531.1 FL58.2 U154.14(VCCDA1) U154.34(VCCDA2)
AOUT1_a: C1242.1 R1272.2 R1276.1 R1279.1 R1283.1
AOUT1_b: C1242.2 R1271.2 R1275.1 R1279.2 R1282.1
AOUT1_c: C1234.2 R1272.1 U267.6(-INB)
AOUT1_d: C1233.1 R1271.1 U267.5(+INB)
AOUT1_e: C1233.2 R1273.2 R1274.1 R1275.2
AOUT1_N: C1263.2 U154.32(VOUT1-)
AOUT1_o: C1229.1 C1234.1 R1276.2 U267.7(OUTB)
AOUT1_P: C1262.2 U154.31(VOUT1+)
AOUT1N: C1263.1 R1283.2
AOUT1P: C1262.1 R1282.2
AOUT2_a: C1193.1 R1219.1 R1226.1 R1237.1 R1239.2
AOUT2_b: C1193.2 R1222.1 R1226.2 R1236.1 R1238.2
AOUT2_c: C1202.2 R1239.1 U267.2(-INA)
AOUT2_d: C1201.1 R1238.1 U267.3(+INA)
AOUT2_e: C1201.2 R1229.1 R1230.2 R1236.2
AOUT2_N: C1194.2 U154.30(VOUT2-)
AOUT2_o: C1202.1 C1215.1 R1237.2 U267.1(OUTA)
AOUT2_P: C1195.2 U154.29(VOUT2+)
AOUT2N: C1194.1 R1219.2
AOUT2P: C1195.1 R1222.2
AUDIO_EXT_REFCLK1: U154.41(SCKI) ; also on sheet 48
CODEC_I2C_ADR0: R693.2 R694.1 U154.45(MS/ADR0/MD0)
CODEC_I2C_ADR1: R698.2 R699.1 U154.44(MDO/ADR1/MD1)
CODEC_MODE: R687.1 R688.2 U154.48(MODE)
CODEC_OVF: TP245.1(TP) U154.5(OVF)
CODEC_RSTz: R695.2 TP231.1(TP) U154.4(RST#) ; also on sheet 38
CODEC_VREFAD1: C1227.1 U154.59(VREFAD1)
CODEC_VREFAD2: C484.1 U154.60(VREFAD2)
CODEC_ZERO: TP247.1(TP) U154.13(ZERO)
I2C3_SCL: U154.42(MC/SCL/FMT) ; also on sheet 20 38
I2C3_SDA: U154.43(MDI/SDA/DEMP) ; also on sheet 20 38
LINE_OUT2_L: C1229.2 J29.5B R1263.1
LINE_OUT2_R: C1215.2 J29.2B R1252.1
MCASP0_ACLKX: TP212.1(TP) U154.7(BCKAD) U154.36(BCKDA) ; also on sheet 48
MCASP0_AFSX: TP217.1(TP) U154.6(LRCKAD) U154.35(LRCKDA) ; also on sheet 48
MCASP0_AXR3: U154.37(DIN1) ; also on sheet 48
MCASP0_AXR4: R705.2 ; also on sheet 48
MCASP0_AXR4_R: R705.1 U154.8(DOUT1)
MIC1_L_N: U154.51(VIN1-) ; also on sheet 84
MIC1_L_P: U154.52(VIN1+) ; also on sheet 84
MIC1_R_N: U154.53(VIN2-) ; also on sheet 84
MIC1_R_P: U154.54(VIN2+) ; also on sheet 84
VCOMAD: U136.1(OUTA) U136.2(-INA) ; also on sheet 84
VCOMAD_CODEC: C1238.1 U136.3(+INA) U136.5(+INB) U154.1(VCOMAD)
VCOMAD_SPARE: TP233.1(TP) U136.6(-INB) U136.7(OUTB)
VCOMDA: C544.1 U154.15(VCOMDA)
VSYS_5V0: C413.1 C414.1 C467.1 C524.1 FL56.1 FL57.1 FL58.1 ; also on sheet 20 30 31 50 52 59 65 68 72 81 84
VSYS_IO_3V3: C507.1 C520.1 C1240.1 R688.1 R694.2 R699.2 U154.12(VDD2) U154.46(VDD1) ; also on sheet 18 20 22 24 29 30 31 32 33 35 36 37 38 40 41 42 43 45 46 48 50 51 53 56 57 58 59 60 61 65 66 68 75 81

Not connected (* = marked no-connect by the designer): U154 9(DOUT2)* 10(DOUT3)* 17(VOUT8+)* 18(VOUT8-)* 19(VOUT7+)* 20(VOUT7-)* 21(VOUT6+)* 22(VOUT6-)* 23(VOUT5+)* 24(VOUT5-)* 25(VOUT4+)* 26(VOUT4-)* 27(VOUT3+)* 28(VOUT3-)* 38(DIN2)* 39(DIN3)* 40(DIN4)* 55(VIN3-)* 56(VIN3+)* 57(VIN4-)* 58(VIN4+)* 61(VIN5-)* 62(VIN5+)* 63(VIN6-)* 64(VIN6+)*

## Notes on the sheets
sheet 82
- AUDIO I/F CODEC
- 1x STEREO MIC-IN
- 1x HEADPHONE OUT
- [Codec MCLK]
- From IO EXP
- PCB Note: Short CODEC_AGND and DGND at single point
- I2C Address SEL
- MODE tied to DGND with 0E Resistor for Software Control (default)
- 7b' I2C Address 0x44 (default)
sheet 83
- AUDIO I/F - STEREO HEADPHONE OUT # 1
- 2 Vrms
- 8Vpp Differential
- Gain = 0.747; f–3 dB = 53 kHz
- J29 Bottom Jack
  HPOUT L VOUT1
  HPOUT R VOUT2
- Gain = 0.747; f–3 dB = 53 kHz
- 8Vpp Differential
